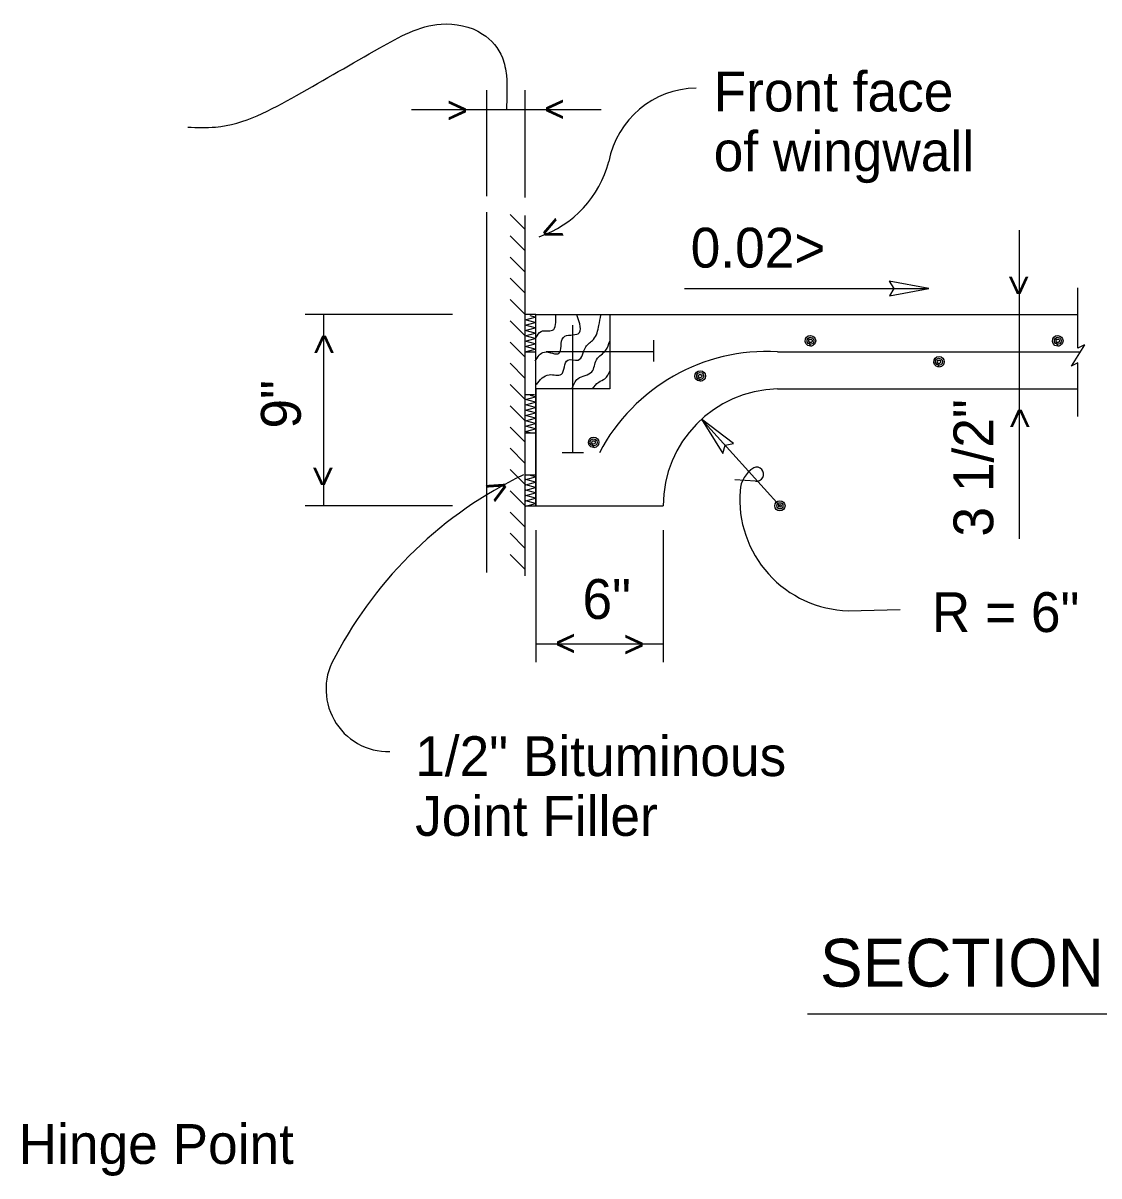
# Model space of a CAD drawing. Extents: x 0 to 3.31, y -0.03 to 1.83.
# Drawn here: x 1.248 to 1.5998, y 0.4764 to 0.8531 of the extents above; entities that cross this region are included whole.
import ezdxf

# ---------------------------------------------------------------- set-up
doc = ezdxf.new("R2010")
doc.units = 0
for name, color, linetype in [('50', 7, 'Continuous'), ('51', 7, 'Continuous'), ('54', 7, 'Continuous'), ('55', 7, 'Continuous'), ('57', 7, 'Continuous')]:
    doc.layers.add(name, color=color, linetype=linetype)

msp = doc.modelspace()

# ---------------------------------------------------------------- linework, layer by layer
at = {"layer": '50'}
for p, q in [((1.3996555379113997, 0.6735277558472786), (1.3996555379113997, 0.7912860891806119)), ((1.4121472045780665, 0.672511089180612), (1.4121472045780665, 0.7902694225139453)), ((1.4156222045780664, 0.7578527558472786), (1.4121472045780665, 0.7578527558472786)), ((1.4156222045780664, 0.6953527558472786), (1.4156222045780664, 0.7578527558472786)), ((1.4399222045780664, 0.7578527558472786), (1.592896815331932, 0.7578527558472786)), ((1.4122138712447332, 0.7456944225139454), (1.4154638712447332, 0.7456944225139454)), ((1.4946805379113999, 0.7457027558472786), (1.5936597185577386, 0.7457027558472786)), ((1.4119472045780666, 0.7317194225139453), (1.4151972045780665, 0.7317194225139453)), ((1.4156222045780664, 0.7335527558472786), (1.4156222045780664, 0.6953527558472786)), ((1.4946805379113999, 0.7335527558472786), (1.592896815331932, 0.7335527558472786)), ((1.412263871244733, 0.719186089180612), (1.415513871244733, 0.719186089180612)), ((1.4121305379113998, 0.705461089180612), (1.4153805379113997, 0.705461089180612)), ((1.4123722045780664, 0.6953527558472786), (1.4156222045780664, 0.6953527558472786)), ((1.4156222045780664, 0.6953527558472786), (1.4572888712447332, 0.6953527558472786))]:
    msp.add_line(p, q, dxfattribs=at)
for points in [[(1.4122138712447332, 0.7456944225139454), (1.4154638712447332, 0.7465694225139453), (1.4122138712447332, 0.747436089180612), (1.4154638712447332, 0.7482944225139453), (1.4122138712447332, 0.7491694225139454), (1.4154638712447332, 0.7500360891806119), (1.4122138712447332, 0.7508944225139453), (1.4154638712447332, 0.7517694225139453), (1.4122138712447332, 0.752636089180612), (1.4154638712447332, 0.7534944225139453), (1.4122138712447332, 0.7543694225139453), (1.4154638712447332, 0.755236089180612), (1.4122138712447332, 0.7561027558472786), (1.4154638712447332, 0.7569694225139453), (1.4138222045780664, 0.757411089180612)], [(1.4123388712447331, 0.7196527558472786), (1.415588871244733, 0.7205194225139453), (1.4123388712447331, 0.721386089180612), (1.415588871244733, 0.7222527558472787), (1.4123388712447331, 0.7231194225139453), (1.415588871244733, 0.7239944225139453), (1.4123388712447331, 0.7248527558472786), (1.415588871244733, 0.7257277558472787), (1.4123388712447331, 0.7265944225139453), (1.415588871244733, 0.7274527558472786), (1.4123388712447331, 0.7283277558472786), (1.415588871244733, 0.7291944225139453), (1.4123388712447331, 0.730061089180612), (1.415588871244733, 0.7309277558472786), (1.4139388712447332, 0.7313610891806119)], [(1.4138138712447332, 0.7261944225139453), (1.4122138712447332, 0.726611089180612)], [(1.4138138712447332, 0.7192444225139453), (1.4122138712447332, 0.7196694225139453)], [(1.412363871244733, 0.6952944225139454), (1.415613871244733, 0.6961694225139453), (1.412363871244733, 0.697036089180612), (1.415613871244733, 0.6978944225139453), (1.412363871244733, 0.6987694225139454), (1.415613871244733, 0.6996360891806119), (1.412363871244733, 0.7005027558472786), (1.415613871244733, 0.7013694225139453), (1.412363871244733, 0.7022444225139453), (1.415613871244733, 0.7031027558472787), (1.412363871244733, 0.7039777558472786), (1.415613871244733, 0.7048444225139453), (1.413963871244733, 0.7052777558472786)]]:
    msp.add_lwpolyline(points, dxfattribs=at)
msp.add_lwpolyline([(1.4156222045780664, 0.7335527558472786), (1.4156222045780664, 0.7578527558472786), (1.4399222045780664, 0.7578527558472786), (1.4399222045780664, 0.7335527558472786)], close=True, dxfattribs=at)
for centre, radius, start, end in [((1.4913090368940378, 0.6837671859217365), 0.062027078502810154, 86.88734722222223, 152.17821666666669), ((1.4954798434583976, 0.6953555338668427), 0.03819444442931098, 91.20433888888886, 180)]:
    msp.add_arc(centre, radius, start, end, dxfattribs=at)
at = {"layer": '51'}
for p, q in [((1.4277722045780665, 0.7127194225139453), (1.4277722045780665, 0.754386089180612)), ((1.4542555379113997, 0.7425110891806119), (1.4542555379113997, 0.7494527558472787)), ((1.5054555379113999, 0.7492777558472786), (1.5054555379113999, 0.7492777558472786)), ((1.5054555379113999, 0.7492777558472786), (1.5054555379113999, 0.7492777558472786)), ((1.5863218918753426, 0.7492777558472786), (1.5863218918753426, 0.7492777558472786)), ((1.5863218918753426, 0.7492777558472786), (1.5863218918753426, 0.7492777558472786)), ((1.4542555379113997, 0.7457027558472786), (1.4190888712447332, 0.7457027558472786)), ((1.5474888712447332, 0.742436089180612), (1.5474888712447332, 0.742436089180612)), ((1.5474888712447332, 0.742436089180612), (1.5474888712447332, 0.742436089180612)), ((1.469413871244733, 0.7377944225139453), (1.469413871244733, 0.7377944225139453)), ((1.469413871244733, 0.7377944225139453), (1.469413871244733, 0.7377944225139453)), ((1.4345888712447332, 0.7160944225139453), (1.4345888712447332, 0.7160944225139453)), ((1.4345888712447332, 0.7160944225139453), (1.4345888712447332, 0.7160944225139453)), ((1.4312472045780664, 0.7127194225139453), (1.4242972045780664, 0.7127194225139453))]:
    msp.add_line(p, q, dxfattribs=at)
for points in [[(1.5054472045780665, 0.7475527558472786), (1.5045638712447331, 0.7477944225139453), (1.5039722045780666, 0.7483944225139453), (1.5037305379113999, 0.7490777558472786), (1.5038305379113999, 0.7499027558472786), (1.504213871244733, 0.7504944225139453), (1.5047722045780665, 0.7508777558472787), (1.5054888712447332, 0.751011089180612), (1.5061972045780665, 0.7508444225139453), (1.5067222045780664, 0.7504610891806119), (1.5070472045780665, 0.7499527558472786), (1.5071888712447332, 0.7492944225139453), (1.5070555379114, 0.7486194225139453), (1.5067305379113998, 0.7481360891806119), (1.5062638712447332, 0.7477444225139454), (1.505813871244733, 0.747586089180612), (1.5054972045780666, 0.7475444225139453), (1.5052472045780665, 0.7481444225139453), (1.5047305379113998, 0.7483777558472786), (1.5043555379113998, 0.7489360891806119), (1.5043555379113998, 0.7496194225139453), (1.5046805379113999, 0.7501527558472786), (1.5052805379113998, 0.7504277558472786), (1.5060555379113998, 0.750261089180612), (1.5064555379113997, 0.7498527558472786), (1.5066055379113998, 0.749261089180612), (1.5064555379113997, 0.7487027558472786), (1.506113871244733, 0.748336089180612), (1.5056638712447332, 0.7481360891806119), (1.505263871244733, 0.7481360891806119), (1.5051138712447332, 0.748811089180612), (1.5049055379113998, 0.7491194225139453), (1.5049305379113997, 0.7495110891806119), (1.5052138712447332, 0.7497944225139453), (1.5057055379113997, 0.749786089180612), (1.5059888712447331, 0.7494944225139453), (1.5059805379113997, 0.7490694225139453), (1.5056805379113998, 0.7487527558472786), (1.5053222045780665, 0.7487194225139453), (1.5051138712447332, 0.7487944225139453)], [(1.5863135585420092, 0.7475527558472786), (1.5854302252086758, 0.7477944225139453), (1.584838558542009, 0.7483944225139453), (1.5845968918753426, 0.7490777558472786), (1.5846968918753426, 0.7499027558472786), (1.5850802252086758, 0.7504944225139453), (1.5856385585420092, 0.7508777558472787), (1.586355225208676, 0.751011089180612), (1.5870635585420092, 0.7508444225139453), (1.587588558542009, 0.7504610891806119), (1.5879135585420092, 0.7499527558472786), (1.588055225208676, 0.7492944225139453), (1.5879218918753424, 0.7486194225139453), (1.5875968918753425, 0.7481360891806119), (1.5871302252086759, 0.7477444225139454), (1.5866802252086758, 0.747586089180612), (1.586363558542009, 0.7475444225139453), (1.5861135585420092, 0.7481444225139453), (1.5855968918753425, 0.7483777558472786), (1.5852218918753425, 0.7489360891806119), (1.5852218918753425, 0.7496194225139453), (1.5855468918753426, 0.7501527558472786), (1.5861468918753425, 0.7504277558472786), (1.5869218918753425, 0.750261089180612), (1.5873218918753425, 0.7498527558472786), (1.5874718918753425, 0.749261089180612), (1.5873218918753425, 0.7487027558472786), (1.5869802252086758, 0.748336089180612), (1.586530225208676, 0.7481360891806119), (1.5861302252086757, 0.7481360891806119), (1.5859802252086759, 0.748811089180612), (1.5857718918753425, 0.7491194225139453), (1.5857968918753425, 0.7495110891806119), (1.5860802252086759, 0.7497944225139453), (1.5865718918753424, 0.749786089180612), (1.5868552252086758, 0.7494944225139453), (1.5868468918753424, 0.7490694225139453), (1.5865468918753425, 0.7487527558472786), (1.5861885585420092, 0.7487194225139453), (1.5859802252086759, 0.7487944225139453)], [(1.5474805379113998, 0.740711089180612), (1.5466055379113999, 0.7409527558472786), (1.546013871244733, 0.7415527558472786), (1.5457722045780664, 0.7422277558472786), (1.5458722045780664, 0.743061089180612), (1.5462472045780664, 0.7436527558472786), (1.5468055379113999, 0.7440277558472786), (1.5475222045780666, 0.7441694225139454), (1.5482305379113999, 0.7440027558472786), (1.5487638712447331, 0.743611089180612), (1.549088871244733, 0.743111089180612), (1.5492222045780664, 0.7424527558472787), (1.549088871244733, 0.7417777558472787), (1.5487722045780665, 0.741286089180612), (1.5482972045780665, 0.7409027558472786), (1.5478472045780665, 0.7407444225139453), (1.547538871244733, 0.7407027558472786), (1.5472888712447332, 0.7413027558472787), (1.5467638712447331, 0.741536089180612), (1.5463888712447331, 0.7420944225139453), (1.5463888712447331, 0.7427694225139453), (1.5467222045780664, 0.743311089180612), (1.5473222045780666, 0.743586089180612), (1.5480972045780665, 0.7434194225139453), (1.5484972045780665, 0.743011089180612), (1.5486472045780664, 0.7424110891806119), (1.5484888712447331, 0.741861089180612), (1.5481472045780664, 0.741486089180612), (1.5477055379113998, 0.741286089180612), (1.5472972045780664, 0.741286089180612), (1.5471555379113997, 0.7419694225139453), (1.5469472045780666, 0.7422777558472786), (1.5469722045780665, 0.7426694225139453), (1.5472555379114, 0.7429527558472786), (1.5477472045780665, 0.7429444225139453), (1.5480305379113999, 0.7426444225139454), (1.548013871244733, 0.7422277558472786), (1.5477222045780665, 0.741911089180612), (1.547363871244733, 0.7418694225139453), (1.5471555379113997, 0.7419527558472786)], [(1.4694055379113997, 0.736061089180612), (1.4685305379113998, 0.7363110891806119), (1.4679305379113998, 0.7369027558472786), (1.4676972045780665, 0.737586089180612), (1.4677972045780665, 0.7384110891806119), (1.4681722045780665, 0.739011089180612), (1.4687305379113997, 0.739386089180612), (1.4694472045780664, 0.7395194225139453), (1.4701555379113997, 0.7393610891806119), (1.4706888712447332, 0.7389694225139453), (1.4710138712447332, 0.7384610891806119), (1.4711472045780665, 0.7378027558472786), (1.4710138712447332, 0.7371277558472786), (1.4706972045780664, 0.7366444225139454), (1.4702222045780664, 0.7362527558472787), (1.4697722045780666, 0.7360944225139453), (1.4694638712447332, 0.736061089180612), (1.4692138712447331, 0.7366527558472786), (1.4686888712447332, 0.7368860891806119), (1.4683138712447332, 0.7374444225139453), (1.4683138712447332, 0.7381277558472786), (1.4686388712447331, 0.738661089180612), (1.4692472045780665, 0.7389360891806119), (1.4700222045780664, 0.7387777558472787), (1.4704222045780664, 0.7383610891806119), (1.470563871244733, 0.7377694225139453), (1.4704138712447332, 0.737211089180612), (1.4700722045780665, 0.7368444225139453), (1.4696305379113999, 0.7366444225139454), (1.4692222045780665, 0.7366444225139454), (1.4690805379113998, 0.7373194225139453), (1.468863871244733, 0.737636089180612), (1.4688972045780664, 0.7380194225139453), (1.4691805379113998, 0.738311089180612), (1.4696638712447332, 0.7383027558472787), (1.4699555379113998, 0.7380027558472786), (1.4699388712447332, 0.7375777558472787), (1.4696472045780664, 0.7372694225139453), (1.4692805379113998, 0.7372277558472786), (1.4690805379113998, 0.737311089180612)], [(1.4345805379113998, 0.7143694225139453), (1.4336972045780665, 0.714611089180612), (1.4331055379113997, 0.7152110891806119), (1.4328638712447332, 0.7158944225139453), (1.4329638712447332, 0.7167194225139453), (1.4333472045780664, 0.7173110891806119), (1.4339055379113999, 0.7176944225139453), (1.4346222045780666, 0.7178277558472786), (1.4353305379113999, 0.717661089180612), (1.4358555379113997, 0.7172777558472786), (1.4361805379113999, 0.7167694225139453), (1.4363222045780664, 0.716111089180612), (1.436188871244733, 0.715436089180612), (1.4358638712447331, 0.7149527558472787), (1.4353972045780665, 0.714561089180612), (1.4349472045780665, 0.7144027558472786), (1.4346305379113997, 0.7143610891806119), (1.4343805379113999, 0.714961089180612), (1.4338638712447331, 0.7151944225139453), (1.4334888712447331, 0.7157527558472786), (1.4334888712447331, 0.716436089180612), (1.433813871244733, 0.7169694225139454), (1.4344138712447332, 0.7172444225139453), (1.4351888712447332, 0.7170777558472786), (1.4355972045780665, 0.7166694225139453), (1.4357388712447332, 0.7160777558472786), (1.4355888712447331, 0.7155194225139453), (1.4352472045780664, 0.7151527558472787), (1.4347972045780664, 0.7149527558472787), (1.4343972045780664, 0.7149527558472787), (1.4342472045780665, 0.7156277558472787), (1.4340388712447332, 0.715936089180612), (1.4340638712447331, 0.7163277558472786), (1.4343472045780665, 0.716611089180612), (1.434838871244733, 0.7166027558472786), (1.4351222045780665, 0.7163110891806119), (1.435113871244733, 0.7158860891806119), (1.4348222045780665, 0.7155694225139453), (1.4344555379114, 0.715536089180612), (1.4342472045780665, 0.715611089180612)]]:
    msp.add_lwpolyline(points, dxfattribs=at)
at = {"layer": '54'}
for points in [[(1.5441811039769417, 0.7663463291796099), (1.531189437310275, 0.7687213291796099), (1.5326977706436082, 0.7663463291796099), (1.5313394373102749, 0.7639463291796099)], [(1.469873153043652, 0.7236947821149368), (1.4768209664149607, 0.7124630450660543), (1.477571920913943, 0.7151744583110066), (1.4802633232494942, 0.7157756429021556)]]:
    msp.add_lwpolyline(points, close=True, dxfattribs=at)
at = {"layer": '55'}
for p, q in [((1.3996555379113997, 0.7964944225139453), (1.3996555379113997, 0.831236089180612)), ((1.4121388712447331, 0.7961527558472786), (1.4121388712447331, 0.831236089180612)), ((1.3996555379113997, 0.824761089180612), (1.3749814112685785, 0.824761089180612)), ((1.4121388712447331, 0.824761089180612), (1.3996555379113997, 0.824761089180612)), ((1.4370867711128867, 0.824761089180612), (1.4121388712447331, 0.824761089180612)), ((1.4121472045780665, 0.785636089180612), (1.4072388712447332, 0.7905444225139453)), ((1.4121472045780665, 0.778686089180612), (1.4072388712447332, 0.7836027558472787)), ((1.5737534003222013, 0.7854884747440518), (1.5737534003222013, 0.757811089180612)), ((1.4121472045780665, 0.7717444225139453), (1.4072388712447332, 0.7766527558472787)), ((1.4121472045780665, 0.7648027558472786), (1.4072388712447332, 0.7697110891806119)), ((1.4642578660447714, 0.7663463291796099), (1.5441811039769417, 0.7663463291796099)), ((1.592896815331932, 0.7468777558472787), (1.592896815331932, 0.7666194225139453)), ((1.4121472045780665, 0.7578527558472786), (1.4072388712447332, 0.7627694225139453)), ((1.3883888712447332, 0.7578527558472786), (1.3402888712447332, 0.7578527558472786)), ((1.3462305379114, 0.7577777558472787), (1.3462305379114, 0.6953527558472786)), ((1.5737534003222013, 0.757811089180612), (1.5737534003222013, 0.7335527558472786)), ((1.4121472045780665, 0.750911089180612), (1.4072388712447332, 0.7558194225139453)), ((1.4121472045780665, 0.7439694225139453), (1.4072388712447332, 0.7488777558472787)), ((1.595046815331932, 0.7479527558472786), (1.590746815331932, 0.7409777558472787)), ((1.595046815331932, 0.7479527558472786), (1.592896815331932, 0.7468777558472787)), ((1.592871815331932, 0.7444944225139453), (1.592871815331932, 0.7444944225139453)), ((1.4121472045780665, 0.7370194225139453), (1.4072388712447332, 0.7419360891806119)), ((1.5928801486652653, 0.7420944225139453), (1.590746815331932, 0.7409777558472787)), ((1.592896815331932, 0.7245078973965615), (1.592896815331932, 0.742111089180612)), ((1.4121472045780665, 0.7300777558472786), (1.4072388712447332, 0.7349860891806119)), ((1.5737534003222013, 0.7335527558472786), (1.5737534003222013, 0.6845672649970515)), ((1.4121472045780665, 0.723136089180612), (1.4072388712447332, 0.7280444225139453)), ((1.4954798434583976, 0.6953555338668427), (1.469873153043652, 0.7236947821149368)), ((1.4121472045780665, 0.716186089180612), (1.4072388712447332, 0.7211027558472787)), ((1.4121472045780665, 0.7092444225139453), (1.4072388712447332, 0.7141527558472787)), ((1.4121472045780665, 0.7023027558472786), (1.4072388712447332, 0.7072110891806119)), ((1.4874722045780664, 0.7034527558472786), (1.4807972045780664, 0.703861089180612)), ((1.4121472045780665, 0.6953527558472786), (1.4072388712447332, 0.7002694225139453)), ((1.3883888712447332, 0.6953527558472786), (1.3402888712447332, 0.6953527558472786)), ((1.4121472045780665, 0.688411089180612), (1.4072388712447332, 0.6933194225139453)), ((1.4121472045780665, 0.6814694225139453), (1.4072388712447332, 0.6863777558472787)), ((1.4156222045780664, 0.687386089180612), (1.4156222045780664, 0.644311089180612)), ((1.4572888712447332, 0.687386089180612), (1.4572888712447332, 0.644311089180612)), ((1.4121472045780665, 0.6745194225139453), (1.4072388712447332, 0.6794360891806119)), ((1.5178555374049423, 0.6611027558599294), (1.5347665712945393, 0.6614407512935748)), ((1.4574055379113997, 0.650211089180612), (1.4157388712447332, 0.650211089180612))]:
    msp.add_line(p, q, dxfattribs=at)
for radius in [0.0016804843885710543, 0.001013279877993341, 0.0004194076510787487]:
    msp.add_circle((1.4954798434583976, 0.6953555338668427), radius, dxfattribs=at)
for centre, radius, start, end in [((1.4686040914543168, 0.8022672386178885), 0.02960995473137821, 91.01840555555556, 169.07751666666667), ((1.4053731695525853, 0.816687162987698), 0.03527508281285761, 288.86825, 345.53819444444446), ((1.4700127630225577, 0.5833460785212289), 0.13535313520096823, 115.55998333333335, 152.19372222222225), ((1.4920831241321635, 0.699678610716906), 0.009646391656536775, 122.34641111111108, 176.53178055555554), ((1.4878514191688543, 0.70571514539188), 0.0023010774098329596, 260.5684527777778, 113.61206944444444), ((1.5188017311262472, 0.6975458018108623), 0.03645532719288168, 175.72758333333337, 268.51272777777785), ((1.3674980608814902, 0.635465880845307), 0.02043529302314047, 147.36581666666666, 271.3295083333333)]:
    msp.add_arc(centre, radius, start, end, dxfattribs=at)
for points in [[(1.3018782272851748, 0.819128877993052), (1.3109352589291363, 0.819128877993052), (1.3374594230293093, 0.8294797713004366), (1.364630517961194, 0.8450061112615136), (1.384685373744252, 0.8527692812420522), (1.3982709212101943, 0.8495346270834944), (1.4047402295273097, 0.8417714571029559), (1.4060340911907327, 0.835949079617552), (1.4060340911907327, 0.8247610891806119)], [(1.4154805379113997, 0.742636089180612), (1.418463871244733, 0.7456194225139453), (1.423238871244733, 0.7451444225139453), (1.4246722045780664, 0.7503944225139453), (1.4295638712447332, 0.7515944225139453), (1.4290888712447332, 0.757736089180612)], [(1.4157222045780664, 0.7502194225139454), (1.4174472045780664, 0.7523694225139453), (1.4210888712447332, 0.7527277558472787), (1.422163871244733, 0.757736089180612)], [(1.4158388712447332, 0.7349944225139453), (1.4200722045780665, 0.7382194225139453), (1.4240138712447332, 0.738336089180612), (1.4261055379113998, 0.7429944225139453), (1.4295055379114, 0.7429944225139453), (1.4320138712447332, 0.7472944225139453), (1.4345222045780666, 0.749736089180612), (1.4363138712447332, 0.754336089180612), (1.4369055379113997, 0.7576777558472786)], [(1.4274805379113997, 0.733561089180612), (1.4294472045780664, 0.736911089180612), (1.4339805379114, 0.7391777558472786), (1.4355388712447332, 0.743111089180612), (1.4385805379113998, 0.7462194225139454), (1.4398305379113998, 0.7491444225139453)], [(1.4342222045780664, 0.733561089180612), (1.4362472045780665, 0.7357694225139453), (1.4382805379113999, 0.736911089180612), (1.439888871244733, 0.7394110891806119)]]:
    msp.add_spline(points, degree=3, dxfattribs=at)
at = {"layer": '57'}
msp.add_line((1.5045064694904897, 0.5293479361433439), (1.6765731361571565, 0.5293479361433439), dxfattribs=at)

# ---------------------------------------------------------------- texts
at = {"layer": '55'}
for p in [(1.386638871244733, 0.8204277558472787), (1.444388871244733, 0.6458777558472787), (1.444388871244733, 0.6458777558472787)]:
    msp.add_text('>', height=0.008675, dxfattribs=at).set_placement(p)
for height, rotation, p in [(0.008675, 180, (1.4251555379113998, 0.8290944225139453)), (0.0086792, 204.7930749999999, (1.4221972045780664, 0.7905944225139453)), (0.0086792, 204.7930749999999, (1.4221972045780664, 0.7905944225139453)), (0.008675, 270, (1.569420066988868, 0.7708277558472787)), (0.008675, 270, (1.569420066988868, 0.7708277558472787)), (0.008675, 90, (1.3505638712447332, 0.744761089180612)), (0.008675, 90, (1.3505638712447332, 0.744761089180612)), (0.008675, 90, (1.5780867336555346, 0.720536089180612)), (0.008675, 90, (1.5780867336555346, 0.720536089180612)), (0.008675, 270, (1.3418972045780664, 0.7083694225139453)), (0.008675, 270, (1.3418972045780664, 0.7083694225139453)), (0.00867285, 28.53433055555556, (1.4022555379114, 0.6954194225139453)), (0.00867285, 28.53433055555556, (1.4022555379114, 0.6954194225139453)), (0.008675, 180, (1.4287555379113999, 0.6545444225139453)), (0.008675, 180, (1.4287555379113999, 0.6545444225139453))]:
    msp.add_text('>', height=height, rotation=rotation, dxfattribs=at).set_placement(p)
at = {"layer": '57'}
for s, height, p in [('Front face', 0.013016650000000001, (1.4738388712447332, 0.824236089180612)), ('of wingwall', 0.013016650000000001, (1.4738388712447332, 0.804711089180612)), ('0.02>', 0.013016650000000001, (1.466312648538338, 0.7732039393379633)), ('6"', 0.013016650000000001, (1.4309305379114, 0.6584088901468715)), ('R = 6"', 0.013016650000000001, (1.5451571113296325, 0.6541192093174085)), ('1/2" Bituminous', 0.013016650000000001, (1.3762222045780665, 0.6070527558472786)), ('Joint Filler', 0.013016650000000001, (1.3762222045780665, 0.5875277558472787)), ('SECTION B-B', 0.015625, (1.5085898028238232, 0.5382562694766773)), ('Hinge Point', 0.013016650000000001, (1.2465702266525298, 0.4803194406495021))]:
    msp.add_text(s, height=height, dxfattribs=at).set_placement(p)
for s, p in [('9"', (1.3388077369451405, 0.7206027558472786)), ('3 1/2"', (1.5652554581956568, 0.6853146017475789))]:
    msp.add_text(s, height=0.013016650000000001, rotation=90, dxfattribs=at).set_placement(p)

doc.saveas('drawing.dxf')
